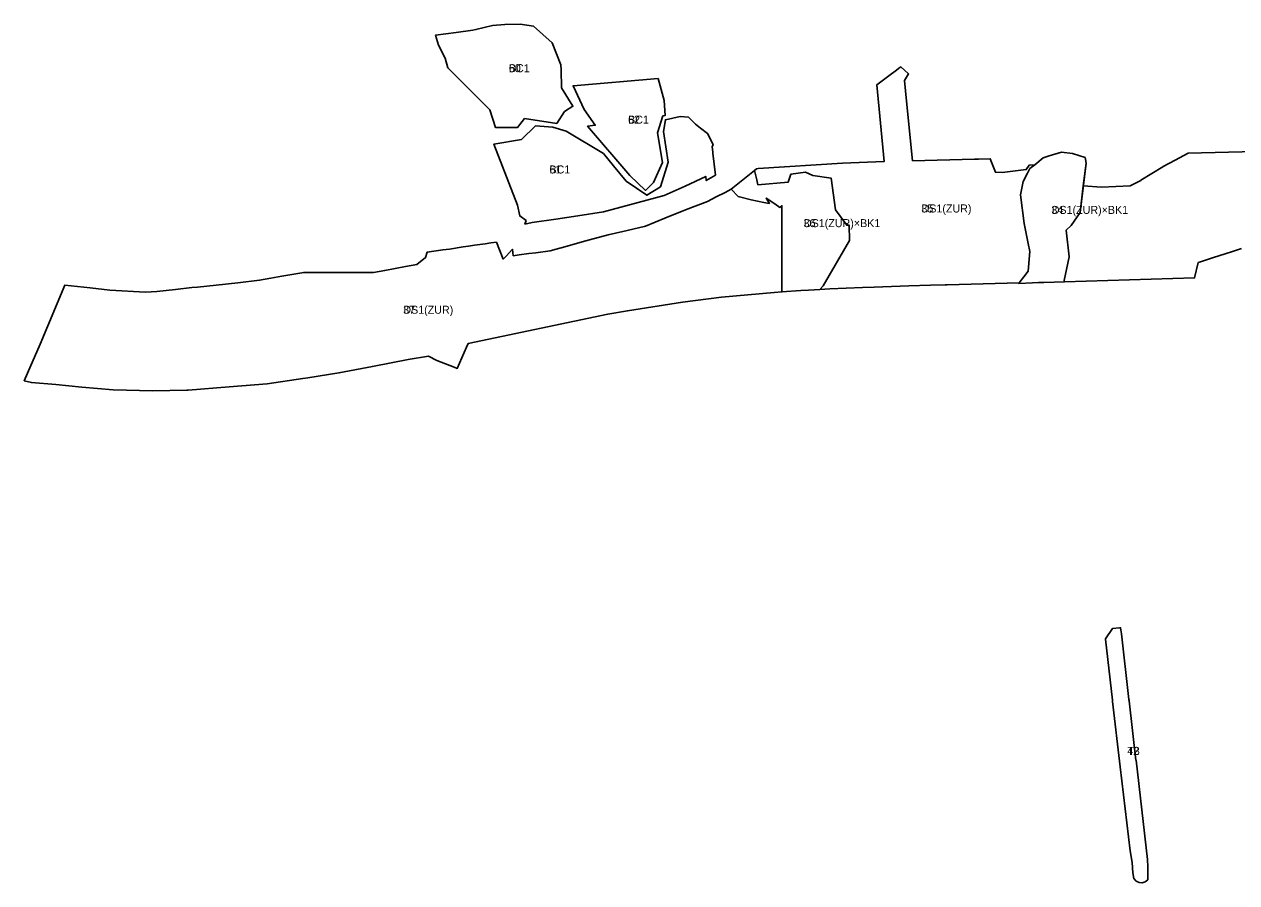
# Model space of a CAD drawing. Extents: x -501732 to -497651, y -1141409 to -1138069.
# Drawn here: x -500076 to -498863, y -1141346 to -1140487 of the extents above; entities that cross this region are included whole.
import ezdxf

# ---------------------------------------------------------------- set-up
doc = ezdxf.new("R2010")
doc.units = 0
for name, color, linetype in [('51', 7, 'Continuous'), ('57', 7, 'Continuous'), ('59', 7, 'Continuous'), ('61', 7, 'Continuous'), ('62', 7, 'Continuous')]:
    doc.layers.add(name, color=color, linetype=linetype)

msp = doc.modelspace()

# ---------------------------------------------------------------- linework, layer by layer
at = {"layer": '51'}
for points in [[(-499193.743, -1140564.164), (-499187.593, -1140623.765), (-499125.613, -1140622.084), (-499121.498, -1140622.007), (-499109.83, -1140621.793), (-499104.775, -1140635.27), (-499098.12, -1140635.51), (-499073.93, -1140632.6), (-499071.1, -1140628.29), (-499065.36, -1140627.7), (-499070.17, -1140631.57), (-499072.58, -1140636.22), (-499076.87, -1140644.51), (-499079.52, -1140657.94), (-499076.12, -1140686.47), (-499074.73, -1140693.14), (-499071.93, -1140706.5), (-499070.28, -1140714.4), (-499071.9, -1140734.07), (-499076.35, -1140739.92), (-499079.831, -1140744.505), (-499080.879, -1140745.886), (-499152.805, -1140747.86), (-499154.982, -1140747.925), (-499169.782, -1140748.335), (-499191.197, -1140748.979), (-499226.049, -1140750.027), (-499237.616, -1140750.501), (-499270.129, -1140751.834), (-499280.121, -1140752.464), (-499277.06, -1140748.76), (-499250.63, -1140703.66), (-499251.1, -1140688), (-499253.41, -1140688.26), (-499264.63, -1140672.68), (-499268.97, -1140641.12), (-499287.15, -1140638.53), (-499294.64, -1140635.04), (-499309.22, -1140637.3), (-499311.8, -1140645.11), (-499342.17, -1140647.8), (-499343.34, -1140642.72), (-499345.45, -1140633.59), (-499343.452, -1140631.948), (-499341.787, -1140631.307), (-499257.506, -1140626.19), (-499215.96, -1140624.634), (-499223.15, -1140547.739), (-499223.155, -1140547.686), (-499220.46, -1140545.72), (-499209.99, -1140537.82), (-499205.05, -1140534.1), (-499200.19, -1140530.44), (-499199.435, -1140529.871), (-499191.53, -1140536.772), (-499195.631, -1140543.336)], [(-499067.685, -1140745.918), (-499081.3, -1140746.44), (-499080.879, -1140745.886), (-499079.831, -1140744.505), (-499076.35, -1140739.92), (-499071.9, -1140734.07), (-499070.28, -1140714.4), (-499071.93, -1140706.5), (-499074.73, -1140693.14), (-499076.12, -1140686.47), (-499079.52, -1140657.94), (-499076.87, -1140644.51), (-499072.58, -1140636.22), (-499070.17, -1140631.57), (-499065.36, -1140627.7), (-499056.95, -1140620.92), (-499050.8, -1140618.95), (-499038.79, -1140615.12), (-499027.65, -1140616.56), (-499021.444, -1140618.517), (-499015.06, -1140620.53), (-499014.095, -1140625.974), (-499020.1, -1140675.56), (-499029, -1140688.61), (-499033.93, -1140693.11), (-499030.81, -1140719.88), (-499035.84, -1140743.39), (-499035.689, -1140744.86), (-499056.3, -1140745.482), (-499061.682, -1140745.688)], [(-499343.34, -1140642.72), (-499342.17, -1140647.8), (-499311.8, -1140645.11), (-499309.22, -1140637.3), (-499294.64, -1140635.04), (-499287.15, -1140638.53), (-499268.97, -1140641.12), (-499264.63, -1140672.68), (-499253.41, -1140688.26), (-499251.1, -1140688), (-499250.63, -1140703.66), (-499277.06, -1140748.76), (-499280.121, -1140752.464), (-499291.492, -1140753.18), (-499299.376, -1140753.677), (-499318.205, -1140754.864), (-499318.17, -1140668.78), (-499320.15, -1140670.38), (-499325.18, -1140666.98), (-499333.87, -1140661.11), (-499330.61, -1140666.33), (-499336.17, -1140665.33), (-499348.98, -1140662.77), (-499361.92, -1140659.52), (-499368.85, -1140652.22), (-499345.45, -1140633.59)], [(-499336.17, -1140665.33), (-499330.61, -1140666.33), (-499333.87, -1140661.11), (-499325.18, -1140666.98), (-499320.15, -1140670.38), (-499318.17, -1140668.78), (-499318.205, -1140754.864), (-499325.955, -1140755.459), (-499378.578, -1140760.25), (-499417.449, -1140765.058), (-499472.628, -1140773.759), (-499492.357, -1140777.353), (-499631.938, -1140806.639), (-499633.456, -1140810.077), (-499642.91, -1140831.49), (-499645.82, -1140830.36), (-499663.37, -1140823.5), (-499671.468, -1140819.249), (-499691.891, -1140822.595), (-499727.587, -1140829.446), (-499761.116, -1140835.905), (-499792.321, -1140840.954), (-499797.177, -1140841.705), (-499832.873, -1140846.753), (-499870.733, -1140849.998), (-499911.876, -1140853.136), (-499913.28, -1140853.243), (-499947.173, -1140853.965), (-499986.836, -1140852.883), (-500018.205, -1140850.359), (-500044.166, -1140847.474), (-500068.684, -1140845.671), (-500075.798, -1140843.893), (-500072.57, -1140836.37), (-500059.78, -1140807.23), (-500035.06, -1140748.07), (-500010.02, -1140750.97), (-499990.38, -1140753.25), (-499954.68, -1140755.08), (-499943.15, -1140754.4), (-499924.56, -1140752.4), (-499908.18, -1140750.67), (-499902.55, -1140750.07), (-499883.97, -1140748.1), (-499862.11, -1140745.79), (-499840.49, -1140743.2), (-499829.08, -1140741.17), (-499818.17, -1140739.23), (-499796.39, -1140735.36), (-499783.77, -1140735.66), (-499771.57, -1140735.61), (-499761.35, -1140735.57), (-499749.76, -1140735.53), (-499738.77, -1140735.49), (-499726.7, -1140735.44), (-499715.41, -1140733.37), (-499694.56, -1140729.55), (-499683.08, -1140727.45), (-499674.69, -1140720.64), (-499673.01, -1140715.31), (-499657.17, -1140712.96), (-499650.74, -1140712.01), (-499637.07, -1140709.98), (-499631.48, -1140709.15), (-499625.55, -1140708.27), (-499615.02, -1140706.71), (-499609.18, -1140705.84), (-499603.59, -1140705.01), (-499596.76, -1140722.05), (-499593.97, -1140719.05), (-499587.68, -1140712.31), (-499586.84, -1140718.68), (-499580.78, -1140717.89), (-499571.12, -1140716.63), (-499564.22, -1140715.73), (-499549.94, -1140713.97), (-499543.93, -1140712.26), (-499535.12, -1140709.81), (-499517.78, -1140705), (-499510.437, -1140702.959), (-499491.91, -1140697.81), (-499477.31, -1140694.47), (-499455.81, -1140689.52), (-499454.65, -1140689.07), (-499435.14, -1140681), (-499414.46, -1140672.94), (-499392.67, -1140664.44), (-499383.82, -1140659.9), (-499375.03, -1140655.39), (-499368.85, -1140652.22), (-499361.92, -1140659.52), (-499348.98, -1140662.77)], [(-498971.151, -1141162.829), (-498971.049, -1141163.707), (-498971.021, -1141163.944), (-498964.157, -1141223.283), (-498964.136, -1141223.466), (-498952.662, -1141322.649), (-498952.505, -1141324.009), (-498952.437, -1141328.802), (-498952.38, -1141332.83), (-498952.45, -1141342.993), (-498955.014, -1141345.143), (-498957.963, -1141346.07), (-498961.047, -1141345.847), (-498964.038, -1141344.347), (-498966.187, -1141341.783), (-498967.437, -1141336.081), (-498968.043, -1141325.881), (-498970.019, -1141313.972), (-498979.825, -1141230.048), (-498979.839, -1141229.927), (-498987.473, -1141164.587), (-498987.577, -1141163.696), (-498987.66, -1141163.7), (-498987.622, -1141163.31), (-498994.728, -1141102.49), (-498994.791, -1141101.957), (-498987.682, -1141091.711), (-498980.599, -1141090.99), (-498979.474, -1141090.876), (-498978.75, -1141097.133)]]:
    msp.add_lwpolyline(points, close=True, dxfattribs=at)
msp.add_lwpolyline([(-498858.59, -1140711.59), (-498868.78, -1140714.9), (-498886.5, -1140720.67), (-498899.62, -1140724.8), (-498901.91, -1140725.52), (-498905.517, -1140740.941), (-499035.689, -1140744.86), (-499035.84, -1140743.39), (-499030.81, -1140719.88), (-499033.93, -1140693.11), (-499029, -1140688.61), (-499020.1, -1140675.56), (-499016.846, -1140648.693), (-498998.708, -1140650.243), (-498969.961, -1140648.733), (-498959.33, -1140643.34), (-498959.23, -1140643.29), (-498937.32, -1140629.72), (-498937.03, -1140629.54), (-498924.99, -1140623.14), (-498911.97, -1140616.22), (-498763.779, -1140612.414)], dxfattribs=at)
at = {"layer": '57'}
for points in [[(-499566.62, -1140489.06), (-499547.88, -1140505.67), (-499539.12, -1140527.68), (-499539.028, -1140532.751), (-499538.7, -1140550.93), (-499527.18, -1140569.27), (-499535.57, -1140574.57), (-499543.26, -1140586.53), (-499575.43, -1140581.51), (-499582.54, -1140590.43), (-499604.53, -1140590.48), (-499610.15, -1140572.87), (-499652.39, -1140530.78), (-499655.08, -1140521.18), (-499661.73, -1140508.09), (-499664.44, -1140498.01), (-499644.04, -1140495.57), (-499627.33, -1140493.08), (-499624.23, -1140492.57), (-499607.55, -1140488.51), (-499595.1, -1140487.47), (-499579.78, -1140487.14)], [(-499446.49, -1140645.45), (-499454.54, -1140653.33), (-499470.13, -1140638.41), (-499512.49, -1140589.17), (-499504.86, -1140588.13), (-499515.93, -1140572.31), (-499526.97, -1140548.74), (-499442, -1140541.58), (-499435.93, -1140563.57), (-499434.93, -1140578.4), (-499437.1, -1140578.87), (-499442.64, -1140595.64), (-499437.57, -1140625.52)], [(-499384.44, -1140638.12), (-499393.83, -1140643.64), (-499394.39, -1140639.31), (-499414.88, -1140649.23), (-499436.01, -1140658.54), (-499496.46, -1140674.88), (-499522.13, -1140678.98), (-499544.389, -1140682.197), (-499567.86, -1140685.59), (-499575.14, -1140687.01), (-499574, -1140683.5), (-499580.33, -1140678.85), (-499582.62, -1140668.25), (-499606.15, -1140606.98), (-499578.46, -1140602.36), (-499564.7, -1140588.95), (-499547.17, -1140590.03), (-499534.07, -1140594.13), (-499496.69, -1140616.43), (-499486.551, -1140628.729), (-499473.78, -1140644.22), (-499453.24, -1140658.22), (-499439.58, -1140649.75), (-499431.87, -1140625.18), (-499436.73, -1140594.59), (-499434.63, -1140582.68), (-499420.05, -1140579.58), (-499411.67, -1140580.09), (-499404.71, -1140587.21), (-499399.67, -1140591.011), (-499392.47, -1140596.44), (-499386.97, -1140607.49), (-499387.93, -1140609.82), (-499387.42, -1140614.8), (-499387.28, -1140616.19)], [(-499067.685, -1140745.918), (-499081.3, -1140746.44), (-499080.879, -1140745.886), (-499079.831, -1140744.505), (-499076.35, -1140739.92), (-499071.9, -1140734.07), (-499070.28, -1140714.4), (-499071.93, -1140706.5), (-499074.73, -1140693.14), (-499076.12, -1140686.47), (-499079.52, -1140657.94), (-499076.87, -1140644.51), (-499072.58, -1140636.22), (-499070.17, -1140631.57), (-499065.36, -1140627.7), (-499056.95, -1140620.92), (-499050.8, -1140618.95), (-499038.79, -1140615.12), (-499027.65, -1140616.56), (-499021.444, -1140618.517), (-499015.06, -1140620.53), (-499014.095, -1140625.974), (-499020.1, -1140675.56), (-499029, -1140688.61), (-499033.93, -1140693.11), (-499030.81, -1140719.88), (-499035.84, -1140743.39), (-499035.689, -1140744.86), (-499056.3, -1140745.482), (-499061.682, -1140745.688)], [(-499343.34, -1140642.72), (-499342.17, -1140647.8), (-499311.8, -1140645.11), (-499309.22, -1140637.3), (-499294.64, -1140635.04), (-499287.15, -1140638.53), (-499268.97, -1140641.12), (-499264.63, -1140672.68), (-499253.41, -1140688.26), (-499251.1, -1140688), (-499250.63, -1140703.66), (-499277.06, -1140748.76), (-499280.121, -1140752.464), (-499291.492, -1140753.18), (-499299.376, -1140753.677), (-499318.205, -1140754.864), (-499318.17, -1140668.78), (-499320.15, -1140670.38), (-499325.18, -1140666.98), (-499333.87, -1140661.11), (-499330.61, -1140666.33), (-499336.17, -1140665.33), (-499348.98, -1140662.77), (-499361.92, -1140659.52), (-499368.85, -1140652.22), (-499345.45, -1140633.59)]]:
    msp.add_lwpolyline(points, close=True, dxfattribs=at)
at = {"layer": '59'}
for points in [[(-499566.62, -1140489.06), (-499547.88, -1140505.67), (-499539.12, -1140527.68), (-499539.028, -1140532.751), (-499538.7, -1140550.93), (-499527.18, -1140569.27), (-499535.57, -1140574.57), (-499543.26, -1140586.53), (-499575.43, -1140581.51), (-499582.54, -1140590.43), (-499604.53, -1140590.48), (-499610.15, -1140572.87), (-499652.39, -1140530.78), (-499655.08, -1140521.18), (-499661.73, -1140508.09), (-499664.44, -1140498.01), (-499644.04, -1140495.57), (-499627.33, -1140493.08), (-499624.23, -1140492.57), (-499607.55, -1140488.51), (-499595.1, -1140487.47), (-499579.78, -1140487.14)], [(-499446.49, -1140645.45), (-499454.54, -1140653.33), (-499470.13, -1140638.41), (-499512.49, -1140589.17), (-499504.86, -1140588.13), (-499515.93, -1140572.31), (-499526.97, -1140548.74), (-499442, -1140541.58), (-499435.93, -1140563.57), (-499434.93, -1140578.4), (-499437.1, -1140578.87), (-499442.64, -1140595.64), (-499437.57, -1140625.52)], [(-499384.44, -1140638.12), (-499393.83, -1140643.64), (-499394.39, -1140639.31), (-499414.88, -1140649.23), (-499436.01, -1140658.54), (-499496.46, -1140674.88), (-499522.13, -1140678.98), (-499544.389, -1140682.197), (-499567.86, -1140685.59), (-499575.14, -1140687.01), (-499574, -1140683.5), (-499580.33, -1140678.85), (-499582.62, -1140668.25), (-499606.15, -1140606.98), (-499578.46, -1140602.36), (-499564.7, -1140588.95), (-499547.17, -1140590.03), (-499534.07, -1140594.13), (-499496.69, -1140616.43), (-499486.551, -1140628.729), (-499473.78, -1140644.22), (-499453.24, -1140658.22), (-499439.58, -1140649.75), (-499431.87, -1140625.18), (-499436.73, -1140594.59), (-499434.63, -1140582.68), (-499420.05, -1140579.58), (-499411.67, -1140580.09), (-499404.71, -1140587.21), (-499399.67, -1140591.011), (-499392.47, -1140596.44), (-499386.97, -1140607.49), (-499387.93, -1140609.82), (-499387.42, -1140614.8), (-499387.28, -1140616.19)], [(-498971.151, -1141162.829), (-498971.049, -1141163.707), (-498971.021, -1141163.944), (-498964.157, -1141223.283), (-498964.136, -1141223.466), (-498952.662, -1141322.649), (-498952.505, -1141324.009), (-498952.437, -1141328.802), (-498952.38, -1141332.83), (-498952.45, -1141342.993), (-498955.014, -1141345.143), (-498957.963, -1141346.07), (-498961.047, -1141345.847), (-498964.038, -1141344.347), (-498966.187, -1141341.783), (-498967.437, -1141336.081), (-498968.043, -1141325.881), (-498970.019, -1141313.972), (-498979.825, -1141230.048), (-498979.839, -1141229.927), (-498987.473, -1141164.587), (-498987.577, -1141163.696), (-498987.66, -1141163.7), (-498987.622, -1141163.31), (-498994.728, -1141102.49), (-498994.791, -1141101.957), (-498987.682, -1141091.711), (-498980.599, -1141090.99), (-498979.474, -1141090.876), (-498978.75, -1141097.133)]]:
    msp.add_lwpolyline(points, close=True, dxfattribs=at)
msp.add_lwpolyline([(-498858.59, -1140711.59), (-498868.78, -1140714.9), (-498886.5, -1140720.67), (-498899.62, -1140724.8), (-498901.91, -1140725.52), (-498905.517, -1140740.941), (-499035.689, -1140744.86), (-499056.3, -1140745.482), (-499061.682, -1140745.688), (-499067.685, -1140745.918), (-499081.3, -1140746.44), (-499080.879, -1140745.886), (-499152.805, -1140747.86), (-499154.982, -1140747.925), (-499169.782, -1140748.335), (-499191.197, -1140748.979), (-499226.049, -1140750.027), (-499237.616, -1140750.501), (-499270.129, -1140751.834), (-499280.121, -1140752.464), (-499291.492, -1140753.18), (-499299.376, -1140753.677), (-499318.205, -1140754.864), (-499325.955, -1140755.459), (-499378.578, -1140760.25), (-499417.449, -1140765.058), (-499472.628, -1140773.759), (-499492.357, -1140777.353), (-499631.938, -1140806.639), (-499633.456, -1140810.077), (-499642.91, -1140831.49), (-499645.82, -1140830.36), (-499663.37, -1140823.5), (-499671.468, -1140819.249), (-499691.891, -1140822.595), (-499727.587, -1140829.446), (-499761.116, -1140835.905), (-499792.321, -1140840.954), (-499797.177, -1140841.705), (-499832.873, -1140846.753), (-499870.733, -1140849.998), (-499911.876, -1140853.136), (-499913.28, -1140853.243), (-499947.173, -1140853.965), (-499986.836, -1140852.883), (-500018.205, -1140850.359), (-500044.166, -1140847.474), (-500068.684, -1140845.671), (-500075.798, -1140843.893), (-500072.57, -1140836.37), (-500059.78, -1140807.23), (-500035.06, -1140748.07), (-500010.02, -1140750.97), (-499990.38, -1140753.25), (-499954.68, -1140755.08), (-499943.15, -1140754.4), (-499924.56, -1140752.4), (-499908.18, -1140750.67), (-499902.55, -1140750.07), (-499883.97, -1140748.1), (-499862.11, -1140745.79), (-499840.49, -1140743.2), (-499829.08, -1140741.17), (-499818.17, -1140739.23), (-499796.39, -1140735.36), (-499783.77, -1140735.66), (-499771.57, -1140735.61), (-499761.35, -1140735.57), (-499749.76, -1140735.53), (-499738.77, -1140735.49), (-499726.7, -1140735.44), (-499715.41, -1140733.37), (-499694.56, -1140729.55), (-499683.08, -1140727.45), (-499674.69, -1140720.64), (-499673.01, -1140715.31), (-499657.17, -1140712.96), (-499650.74, -1140712.01), (-499637.07, -1140709.98), (-499631.48, -1140709.15), (-499625.55, -1140708.27), (-499615.02, -1140706.71), (-499609.18, -1140705.84), (-499603.59, -1140705.01), (-499596.76, -1140722.05), (-499593.97, -1140719.05), (-499587.68, -1140712.31), (-499586.84, -1140718.68), (-499580.78, -1140717.89), (-499571.12, -1140716.63), (-499564.22, -1140715.73), (-499549.94, -1140713.97), (-499543.93, -1140712.26), (-499535.12, -1140709.81), (-499517.78, -1140705), (-499510.437, -1140702.959), (-499491.91, -1140697.81), (-499477.31, -1140694.47), (-499455.81, -1140689.52), (-499454.65, -1140689.07), (-499435.14, -1140681), (-499414.46, -1140672.94), (-499392.67, -1140664.44), (-499383.82, -1140659.9), (-499375.03, -1140655.39), (-499368.85, -1140652.22), (-499345.45, -1140633.59), (-499343.452, -1140631.948), (-499341.787, -1140631.307), (-499257.506, -1140626.19), (-499215.96, -1140624.634), (-499223.15, -1140547.739), (-499223.155, -1140547.686), (-499220.46, -1140545.72), (-499209.99, -1140537.82), (-499205.05, -1140534.1), (-499200.19, -1140530.44), (-499199.435, -1140529.871), (-499191.53, -1140536.772), (-499195.631, -1140543.336), (-499193.743, -1140564.164), (-499187.593, -1140623.765), (-499125.613, -1140622.084), (-499121.498, -1140622.007), (-499109.83, -1140621.793), (-499104.775, -1140635.27), (-499098.12, -1140635.51), (-499073.93, -1140632.6), (-499071.1, -1140628.29), (-499065.36, -1140627.7), (-499056.95, -1140620.92), (-499050.8, -1140618.95), (-499038.79, -1140615.12), (-499027.65, -1140616.56), (-499021.444, -1140618.517), (-499015.06, -1140620.53), (-499014.095, -1140625.974), (-499016.846, -1140648.693), (-498998.708, -1140650.243), (-498969.961, -1140648.733), (-498959.33, -1140643.34), (-498959.23, -1140643.29), (-498937.32, -1140629.72), (-498937.03, -1140629.54), (-498924.99, -1140623.14), (-498911.97, -1140616.22), (-498763.779, -1140612.414)], dxfattribs=at)

# ---------------------------------------------------------------- texts
at = {"layer": '51'}
for s, p in [('DS1(ZUR)', (-499178.566, -1140675.486)), ('DS1(ZUR)×BK1', (-499048.409, -1140676.879)), ('DS1(ZUR)×BK1', (-499296.201, -1140690.147)), ('DS1(ZUR)', (-499696.737, -1140776.777)), ('T3', (-498972.874, -1141218.14))]:
    msp.add_text(s, height=8, dxfattribs=at).set_placement(p)
at = {"layer": '57'}
for s, p in [('BC1', (-499591.186, -1140535.119)), ('BC1', (-499472.012, -1140586.607)), ('BC1', (-499550.61, -1140636.457)), ('DS1(ZUR)×BK1', (-499048.409, -1140676.879)), ('DS1(ZUR)×BK1', (-499296.201, -1140690.147))]:
    msp.add_text(s, height=8, dxfattribs=at).set_placement(p)
at = {"layer": '61'}
for s, p in [('35', (-499178.745, -1140675.486)), ('34', (-499048.722, -1140676.879)), ('36', (-499296.514, -1140690.147)), ('37', (-499696.916, -1140776.777)), ('42', (-498972.874, -1141218.14))]:
    msp.add_text(s, height=8, dxfattribs=at).set_placement(p)
at = {"layer": '62'}
for s, p in [('60', (-499591.231, -1140535.119)), ('62', (-499472.057, -1140586.607)), ('61', (-499550.655, -1140636.457)), ('34', (-499048.722, -1140676.879)), ('36', (-499296.514, -1140690.147))]:
    msp.add_text(s, height=8, dxfattribs=at).set_placement(p)

doc.saveas('drawing.dxf')
